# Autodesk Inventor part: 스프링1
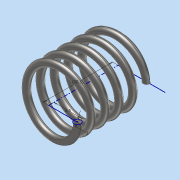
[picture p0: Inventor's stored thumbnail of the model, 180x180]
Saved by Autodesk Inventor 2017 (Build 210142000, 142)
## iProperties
Part Number: 스프링1
Material: 스테인레스 스틸
Document SubType Name: Modeling
Designer: MRC
Density: 8 g/cm^3
Appearance: 반연마
Mass: 6.57569 g
Surface Area: 16.7185 cm^2
Volume: 0.821961 cm^3
Author: MRC
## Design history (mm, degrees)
sketch "스케치1"
  geometry: L1 (0, 0)-(0, 20.5); L2 (0, 0)-(8.5, 0); L3 (0, 20.5)-(14, 20.5); C1 r 1 at (8.5, 0)
  constraints: 6 end point, 2 horizontal, 1 centre point, 1 coincident, 1 vertical
  dimensions: "d0" = 20.5 distance of L1.start L1.end (derived); "d1" = 8.5 distance of L1.start L2.end; "d2" = 2 diameter of C1
feature "코일1" sketch "스케치1" pitch "d3" = 10; turns "d5" = 5; dims "d4" = 20.5 (= d0), "d6" = 0, angle "d7" = 90 deg, angle "d8" = 90 deg, "d9" = 0, "d10" = 0
sketch "스케치2"
  geometry: L1 (20.5, 11)-(0, 11); L2 (0, 11)-(0, -11); L3 (0, -11)-(20.5, -11); L4 (20.5, -11)-(20.5, 11); 2 further points
  constraints: 8 end point, 2 parallel, 1 coincident, 1 horizontal, 1 midpoint, 1 perpendicular
  dimensions: "d11" = 20.5 distance of L2.end L3.end (= d0); "d12" = 22 distance between parallel lines of L3 L1
extrude "돌출1" sketch "스케치2" stored distance "d13" = 50; taper "d14" = 0 deg
node "솔리드1"
